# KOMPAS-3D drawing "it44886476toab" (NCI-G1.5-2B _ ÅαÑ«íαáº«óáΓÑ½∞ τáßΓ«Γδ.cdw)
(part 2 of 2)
  Кривая без истории:10757
  Кривая без истории:10758
  Кривая без истории:10759
  Кривая без истории:10760
  Кривая без истории:10761
  Кривая без истории:10762
  Кривая без истории:10763
  Кривая без истории:10764
  Кривая без истории:10765
  Кривая без истории:10766
  Кривая без истории:10767
  Кривая без истории:10768
  Кривая без истории:10769
  Кривая без истории:10770
  Кривая без истории:10771
  Кривая без истории:10772
  Кривая без истории:10773
  Кривая без истории:10774
  Кривая без истории:10775
  Кривая без истории:10776
  Кривая без истории:10777
  Кривая без истории:10778
  Кривая без истории:10779
  Кривая без истории:10780
  Кривая без истории:10781
  Кривая без истории:10782
  Кривая без истории:10783
  Кривая без истории:10784
  Кривая без истории:10785
  Кривая без истории:10786
  Кривая без истории:10787
  Кривая без истории:10788
  Кривая без истории:10789
  Кривая без истории:10790
  Кривая без истории:10791
  Кривая без истории:10792
  Кривая без истории:10793
  Кривая без истории:10794
  Кривая без истории:10795
  Кривая без истории:10796
  Кривая без истории:10797
  Кривая без истории:10798
  Кривая без истории:10799
  Кривая без истории:10800
  Кривая без истории:10801
  Кривая без истории:10802
  Кривая без истории:10803
  Кривая без истории:10804
  Кривая без истории:10805
  Кривая без истории:10806
  Кривая без истории:10807
  Кривая без истории:10808
  Кривая без истории:10809
  Кривая без истории:10810
  Кривая без истории:10811
  Кривая без истории:10812
  Кривая без истории:10813
  Кривая без истории:10814
  Кривая без истории:10815
  Кривая без истории:10816
  Кривая без истории:10817
  Кривая без истории:10818
  Кривая без истории:10819
  Кривая без истории:10820
  Кривая без истории:10821
  Кривая без истории:10822
  Кривая без истории:10823
  Кривая без истории:10824
  Кривая без истории:10825
  Кривая без истории:10826
  Кривая без истории:10827
  Кривая без истории:10828
  Кривая без истории:10829
  Кривая без истории:10830
  Кривая без истории:10831
  Кривая без истории:10832
  Кривая без истории:10833
  Кривая без истории:10834
  Кривая без истории:10835
  Кривая без истории:10836
  Кривая без истории:10837
  Кривая без истории:10838
  Кривая без истории:10839
  Кривая без истории:10840
  Кривая без истории:10841
  Кривая без истории:10842
  Кривая без истории:10843
  Кривая без истории:10844
  Кривая без истории:10845
  Кривая без истории:10846
  Кривая без истории:10847
  Кривая без истории:10848
  Кривая без истории:10849
  Кривая без истории:10850
  Кривая без истории:10851
  Кривая без истории:10852
  Кривая без истории:10853
  Кривая без истории:10854
  Кривая без истории:10855
  Кривая без истории:10856
  Кривая без истории:10857
  Кривая без истории:10858
  Кривая без истории:10859
  Кривая без истории:10860
  Кривая без истории:10861
  Кривая без истории:10862
  Кривая без истории:10863
  Кривая без истории:10864
  Кривая без истории:10865
  Кривая без истории:10866
  Кривая без истории:10867
  Кривая без истории:10868
  Кривая без истории:10869
  Кривая без истории:10870
  Кривая без истории:10871
  Кривая без истории:10872
  Кривая без истории:10873
  Кривая без истории:10874
  Кривая без истории:10875
  Кривая без истории:10876
  Кривая без истории:10877
  Кривая без истории:10878
  Кривая без истории:10879
  Кривая без истории:10880
  Кривая без истории:10881
  Кривая без истории:10882
  Кривая без истории:10883
  Кривая без истории:10884
  Кривая без истории:10885
  Кривая без истории:10886
  Кривая без истории:10887
  Кривая без истории:10888
  Кривая без истории:10889
  Кривая без истории:10890
  Кривая без истории:10891
  Кривая без истории:10892
  Кривая без истории:10893
  Кривая без истории:10894
  Кривая без истории:10895
  Кривая без истории:10896
  Кривая без истории:10897
  Кривая без истории:10898
  Кривая без истории:10899
  Кривая без истории:10900
  Кривая без истории:10901
  Кривая без истории:10902
  Кривая без истории:10903
  Кривая без истории:10904
  Кривая без истории:10905
  Кривая без истории:10906
  Кривая без истории:10907
  Кривая без истории:10908
  Кривая без истории:10909
  Кривая без истории:10910
  Кривая без истории:10911
  Кривая без истории:10912
  Кривая без истории:10913
  Кривая без истории:10914
  Кривая без истории:10915
  Кривая без истории:10916
  Кривая без истории:10917
  Кривая без истории:10918
  Кривая без истории:10919
  Кривая без истории:10920
  Кривая без истории:10921
  Кривая без истории:10922
  Кривая без истории:10923
  Кривая без истории:10924
  Кривая без истории:10925
  Кривая без истории:10926
  Кривая без истории:10927
  Кривая без истории:10928
  Кривая без истории:10929
  Кривая без истории:10930
  Кривая без истории:10931
  Кривая без истории:10932
  Кривая без истории:10933
  Кривая без истории:10934
  Кривая без истории:10935
  Кривая без истории:10936
  Кривая без истории:10937
  Кривая без истории:10938
  Кривая без истории:10939
  Кривая без истории:10940
  Кривая без истории:10941
  Кривая без истории:10942
  Кривая без истории:10943
  Кривая без истории:10944
  Кривая без истории:10945
  Кривая без истории:10946
  Кривая без истории:10947
  Кривая без истории:10948
  Кривая без истории:10949
  Кривая без истории:10950
  Кривая без истории:10951
  Кривая без истории:10952
  Кривая без истории:10953
  Кривая без истории:10954
  Кривая без истории:10955
  Кривая без истории:10956
  Кривая без истории:10957
  Кривая без истории:10958
  Кривая без истории:10959
  Кривая без истории:10960
  Кривая без истории:10961
  Кривая без истории:10962
  Кривая без истории:10963
  Кривая без истории:10964
  Кривая без истории:10965
  Кривая без истории:10966
  Кривая без истории:10967
  Кривая без истории:10968
  Кривая без истории:10969
  Кривая без истории:10970
  Кривая без истории:10971
  Кривая без истории:10972
  Кривая без истории:10973
  Кривая без истории:10974
  Кривая без истории:10975
  Кривая без истории:10976
  Кривая без истории:10977
  Кривая без истории:10978
  Кривая без истории:10979
  Кривая без истории:10980
  Кривая без истории:10981
  Кривая без истории:10982
  Кривая без истории:10983
  Кривая без истории:10984
  Кривая без истории:10985
  Кривая без истории:10986
  Кривая без истории:10987
  Кривая без истории:10988
  Кривая без истории:10989
  Кривая без истории:10990
  Кривая без истории:10991
  Кривая без истории:10992
  Кривая без истории:10993
  Кривая без истории:10994
  Кривая без истории:10995
  Кривая без истории:10996
  Кривая без истории:10997
  Кривая без истории:10998
  Кривая без истории:10999
  Кривая без истории:11000
  Кривая без истории:11001
  Кривая без истории:11002
  Кривая без истории:11003
  Кривая без истории:11004
  Кривая без истории:11005
  Кривая без истории:11006
  Кривая без истории:11007
  Кривая без истории:11008
  Кривая без истории:11009
  Кривая без истории:11010
  Кривая без истории:11011
  Кривая без истории:11012
  Кривая без истории:11013
  Кривая без истории:11014
  Кривая без истории:11015
  Кривая без истории:11016
  Кривая без истории:11017
  Кривая без истории:11018
  Кривая без истории:11019
  Кривая без истории:11020
  Кривая без истории:11021
  Кривая без истории:11022
  Кривая без истории:11023
  Кривая без истории:11024
  Кривая без истории:11025
  Кривая без истории:11026
  Кривая без истории:11027
  Кривая без истории:11028
  Кривая без истории:11029
  Кривая без истории:11030
  Кривая без истории:11031
  Кривая без истории:11032
  Кривая без истории:11033
  Кривая без истории:11034
  Кривая без истории:11035
  Кривая без истории:11036
  Кривая без истории:11037
  Кривая без истории:11038
  Кривая без истории:11039
  Кривая без истории:11040
  Кривая без истории:11041
  Кривая без истории:11042
  Кривая без истории:11043
  Кривая без истории:11044
  Кривая без истории:11045
  Кривая без истории:11046
  Кривая без истории:11047
  Кривая без истории:11048
  Кривая без истории:11049
  Кривая без истории:11050
  Кривая без истории:11051
  Кривая без истории:11052
  Кривая без истории:11053
  Кривая без истории:11054
  Кривая без истории:11055
  Кривая без истории:11056
  Кривая без истории:11057
  Кривая без истории:11058
  Кривая без истории:11059
  Кривая без истории:11060
  Кривая без истории:11061
  Кривая без истории:11062
  Кривая без истории:11063
  Кривая без истории:11064
  Кривая без истории:11065
  Кривая без истории:11066
  Кривая без истории:11067
  Кривая без истории:11068
  Кривая без истории:11069
  Кривая без истории:11070
  Кривая без истории:11071
  Кривая без истории:11072
  Кривая без истории:11073
  Кривая без истории:11074
  Кривая без истории:11075
  Кривая без истории:11076
  Кривая без истории:11077
  Кривая без истории:11078
  Кривая без истории:11079
  Кривая без истории:11080
  Кривая без истории:11081
  Кривая без истории:11082
  Кривая без истории:11083
  Кривая без истории:11084
  Кривая без истории:11085
  Кривая без истории:11086
  Кривая без истории:11087
  Кривая без истории:11088
  Кривая без истории:11089
  Кривая без истории:11090
  Кривая без истории:11091
  Кривая без истории:11092
  Кривая без истории:11093
  Кривая без истории:11094
  Кривая без истории:11095
  Кривая без истории:11096
  Кривая без истории:11097
  Кривая без истории:11098
  Кривая без истории:11099
  Кривая без истории:11100
  Кривая без истории:11101
  Кривая без истории:11102
  Кривая без истории:11103
  Кривая без истории:11104
  Кривая без истории:11105
  Кривая без истории:11106
  Кривая без истории:11107
  Кривая без истории:11108
  Кривая без истории:11109
  Кривая без истории:11110
  Кривая без истории:11111
  Кривая без истории:11112
  Кривая без истории:11113
  Кривая без истории:11114
  Кривая без истории:11115
  Кривая без истории:11116
  Кривая без истории:11117
  Кривая без истории:11118
  Кривая без истории:11119
  Кривая без истории:11120
  Кривая без истории:11121
  Кривая без истории:11122
  Кривая без истории:11123
  Кривая без истории:11124
  Кривая без истории:11125
  Кривая без истории:11126
  Кривая без истории:11127
  Кривая без истории:11128
  Кривая без истории:11129
  Кривая без истории:11130
  Кривая без истории:11131
  Кривая без истории:11132
  Кривая без истории:11133
  Кривая без истории:11134
  Кривая без истории:11135
  Кривая без истории:11136
  Кривая без истории:11137
  Кривая без истории:11138
  Кривая без истории:11139
  Кривая без истории:11140
  Кривая без истории:11141
  Кривая без истории:11142
  Кривая без истории:11143
  Кривая без истории:11144
  Кривая без истории:11145
  Кривая без истории:11146
  Кривая без истории:11147
  Кривая без истории:11148
  Кривая без истории:11149
  Кривая без истории:11150
  Кривая без истории:11151
  Кривая без истории:11152
  Кривая без истории:11153
  Кривая без истории:11154
  Кривая без истории:11155
  Кривая без истории:11156
  Кривая без истории:11157
  Кривая без истории:11158
  Кривая без истории:11159
  Кривая без истории:11160
  Кривая без истории:11161
  Кривая без истории:11162
  Кривая без истории:11163
  Кривая без истории:11164
  Кривая без истории:11165
  Кривая без истории:11166
  Кривая без истории:11167
  Кривая без истории:11168
  Кривая без истории:11169
  Кривая без истории:11170
  Кривая без истории:11171
  Кривая без истории:11172
  Кривая без истории:11173
  Кривая без истории:11174
  Кривая без истории:11175
  Кривая без истории:11176
  Кривая без истории:11177
  Кривая без истории:11178
  Кривая без истории:11179
  Кривая без истории:11180
  Кривая без истории:11181
  Кривая без истории:11182
  Кривая без истории:11183
  Кривая без истории:11184
  Кривая без истории:11185
  Кривая без истории:11186
  Кривая без истории:11187
  Кривая без истории:11188
  Кривая без истории:11189
  Кривая без истории:11190
  Кривая без истории:11191
  Кривая без истории:11192
  Кривая без истории:11193
  Кривая без истории:11194
  Кривая без истории:11195
  Кривая без истории:11196
  Кривая без истории:11197
  Кривая без истории:11198
  Кривая без истории:11199
  Кривая без истории:11200
  Кривая без истории:11201
  Кривая без истории:11202
  Кривая без истории:11203
  Кривая без истории:11204
  Кривая без истории:11205
  Кривая без истории:11206
  Кривая без истории:11207
  Кривая без истории:11208
  Кривая без истории:11209
  Кривая без истории:11210
  Кривая без истории:11211
  Кривая без истории:11212
  Кривая без истории:11213
  Кривая без истории:11214
  Кривая без истории:11215
  Кривая без истории:11216
  Кривая без истории:11217
  Кривая без истории:11218
  Кривая без истории:11219
  Кривая без истории:11220
  Кривая без истории:11221
  Кривая без истории:11222
  Кривая без истории:11223
  Кривая без истории:11224
  Кривая без истории:11225
  Кривая без истории:11226
  Кривая без истории:11227
  Кривая без истории:11228
  Кривая без истории:11229
  Кривая без истории:11230
  Кривая без истории:11231
  Кривая без истории:11232
  Кривая без истории:11233
  Кривая без истории:11234
  Кривая без истории:11235
  Кривая без истории:11236
  Кривая без истории:11237
  Кривая без истории:11238
  Кривая без истории:11239
  Кривая без истории:11240
  Кривая без истории:11241
  Кривая без истории:11242
  Кривая без истории:11243
  Кривая без истории:11244
  Кривая без истории:11245
  Кривая без истории:11246
  Кривая без истории:11247
  Кривая без истории:11248
  Кривая без истории:11249
  Кривая без истории:11250
  Кривая без истории:11251
  Кривая без истории:11252
  Кривая без истории:11253
  Кривая без истории:11254
  Кривая без истории:11255
  Кривая без истории:11256
  Кривая без истории:11257
  Кривая без истории:11258
  Кривая без истории:11259
  Кривая без истории:11260
  Кривая без истории:11261
  Кривая без истории:11262
  Кривая без истории:11263
  Кривая без истории:11264
  Кривая без истории:11265
  Кривая без истории:11266
  Кривая без истории:11267
  Кривая без истории:11268
  Кривая без истории:11269
  Кривая без истории:11270
  Кривая без истории:11271
  Кривая без истории:11272
  Кривая без истории:11273
  Кривая без истории:11274
  Кривая без истории:11275
  Кривая без истории:11276
  Кривая без истории:11277
  Кривая без истории:11278
  Кривая без истории:11279
  Кривая без истории:11280
  Кривая без истории:11281
  Кривая без истории:11282
  Кривая без истории:11283
  Кривая без истории:11284
  Кривая без истории:11285
  Кривая без истории:11286
  Кривая без истории:11287
  Кривая без истории:11288
  Кривая без истории:11289
  Кривая без истории:11290
  Кривая без истории:11291
  Кривая без истории:11292
  Кривая без истории:11293
  Кривая без истории:11294
  Кривая без истории:11295
  Кривая без истории:11296
  Кривая без истории:11297
  Кривая без истории:11298
  Кривая без истории:11299
  Кривая без истории:11300
  Кривая без истории:11301
  Кривая без истории:11302
  Кривая без истории:11303
  Кривая без истории:11304
  Кривая без истории:11305
  Кривая без истории:11306
  Кривая без истории:11307
  Кривая без истории:11308
  Кривая без истории:11309
  Кривая без истории:11310
  Кривая без истории:11311
  Кривая без истории:11312
  Кривая без истории:11313
  Кривая без истории:11314
  Кривая без истории:11315
  Кривая без истории:11316
  Кривая без истории:11317
  Кривая без истории:11318
  Кривая без истории:11319
  Кривая без истории:11320
  Кривая без истории:11321
  Кривая без истории:11322
  Кривая без истории:11323
  Кривая без истории:11324
  Кривая без истории:11325
  Кривая без истории:11326
  Кривая без истории:11327
  Кривая без истории:11328
  Кривая без истории:11329
  Кривая без истории:11330
  Кривая без истории:11331
  Кривая без истории:11332
  Кривая без истории:11333
  Кривая без истории:11334
  Кривая без истории:11335
  Кривая без истории:11336
  Кривая без истории:11337
  Кривая без истории:11338
  Кривая без истории:11339
  Кривая без истории:11340
  Кривая без истории:11341
  Кривая без истории:11342
  Кривая без истории:11343
  Кривая без истории:11344
  Кривая без истории:11345
  Кривая без истории:11346
  Кривая без истории:11347
  Кривая без истории:11348
  Кривая без истории:11349
  Кривая без истории:11350
  Кривая без истории:11351
  Кривая без истории:11352
  Кривая без истории:11353
  Кривая без истории:11354
  Кривая без истории:11355
  Кривая без истории:11356
  Кривая без истории:11357
  Кривая без истории:11358
  Кривая без истории:11359
  Кривая без истории:11360
  Кривая без истории:11361
  Кривая без истории:11362
  Кривая без истории:11363
  Кривая без истории:11364
  Кривая без истории:11365
  Кривая без истории:11366
  Кривая без истории:11367
  Кривая без истории:11368
  Кривая без истории:11369
  Кривая без истории:11370
  Кривая без истории:11371
  Кривая без истории:11372
  Кривая без истории:11373
  Кривая без истории:11374
  Кривая без истории:11375
  Кривая без истории:11376
  Кривая без истории:11377
  Кривая без истории:11378
  Кривая без истории:11379
  Кривая без истории:11380
  Кривая без истории:11381
  Кривая без истории:11382
  Кривая без истории:11383
  Кривая без истории:11384
  Кривая без истории:11385
  Кривая без истории:11386
  Кривая без истории:11387
  Кривая без истории:11388
  Кривая без истории:11389
  Кривая без истории:11390
  Кривая без истории:11391
  Кривая без истории:11392
  Кривая без истории:11393
  Кривая без истории:11394
  Кривая без истории:11395
  Кривая без истории:11396
  Кривая без истории:11397
  Кривая без истории:11398
  Кривая без истории:11399
  Кривая без истории:11400
  Кривая без истории:11401
  Кривая без истории:11402
  Кривая без истории:11403
  Кривая без истории:11404
  Кривая без истории:11405
  Кривая без истории:11406
  Кривая без истории:11407
  Кривая без истории:11408
  Кривая без истории:11409
  Кривая без истории:11410
  Кривая без истории:11411
  Кривая без истории:11412
  Кривая без истории:11413
  Кривая без истории:11414
  Кривая без истории:11415
  Кривая без истории:11416
  Кривая без истории:11417
  Кривая без истории:11418
  Кривая без истории:11419
  Кривая без истории:11420
  Кривая без истории:11421
  Кривая без истории:11422
  Кривая без истории:11423
  Кривая без истории:11424
  Кривая без истории:11425
  Кривая без истории:11426
  Кривая без истории:11427
  Кривая без истории:11428
  Кривая без истории:11429
  Кривая без истории:11430
  Кривая без истории:11431
  Кривая без истории:11432
  Кривая без истории:11433
  Кривая без истории:11434
  Кривая без истории:11435
  Кривая без истории:11436
  Кривая без истории:11437
  Кривая без истории:11438
  Кривая без истории:11439
  Кривая без истории:11440
  Кривая без истории:11441
  Кривая без истории:11442
  Кривая без истории:11443
  Кривая без истории:11444
  Кривая без истории:11445
  Кривая без истории:11446
  Кривая без истории:11447
  Кривая без истории:11448
  Кривая без истории:11449
  Кривая без истории:11450
  Кривая без истории:11451
  Кривая без истории:11452
  Кривая без истории:11453
  Кривая без истории:11454
  Кривая без истории:11455
  Кривая без истории:11456
  Кривая без истории:11457
  Кривая без истории:11458
  Кривая без истории:11459
  Кривая без истории:11460
  Кривая без истории:11461
  Кривая без истории:11462
  Кривая без истории:11463
  Кривая без истории:11464
  Кривая без истории:11465
  Кривая без истории:11466
  Кривая без истории:11467
  Кривая без истории:11468
  Кривая без истории:11469
  Кривая без истории:11470
  Кривая без истории:11471
  Кривая без истории:11472
  Кривая без истории:11473
  Кривая без истории:11474
  Кривая без истории:11475
  Кривая без истории:11476
  Кривая без истории:11477
  Кривая без истории:11478
  Кривая без истории:11479
  Кривая без истории:11480
  Кривая без истории:11481
  Кривая без истории:11482
  Кривая без истории:11483
  Кривая без истории:11484
  Кривая без истории:11485
  Кривая без истории:11486
  Кривая без истории:11487
  Кривая без истории:11488
  Кривая без истории:11489
  Кривая без истории:11490
  Кривая без истории:11491
  Кривая без истории:11492
  Кривая без истории:11493
  Кривая без истории:11494
  Кривая без истории:11495
  Кривая без истории:11496
  Кривая без истории:11497
  Кривая без истории:11498
  Кривая без истории:11499
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Dimensions and other numbers on the sheet: 4±1; 1:1; 1; 13.01.25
